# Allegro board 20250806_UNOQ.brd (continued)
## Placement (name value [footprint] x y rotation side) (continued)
NOREF#422  -  []  29.56 26.12 90 top
NOREF#423  -  []  15.97 19.8 90 top
NOREF#424  -  []  44.38 16.91 90 top
NOREF#425  -  []  30.56 15.11 90 top
NOREF#426  -  []  35.22 41.52 0 top
NOREF#427  -  []  37.81 10.46 90 top
NOREF#428  -  []  41.28 20.67 90 top
NOREF#429  -  []  43.21 22.16 90 top
NOREF#430  -  []  30.74 33.34 90 top
NOREF#431  -  []  25.85 59.93 0 top
NOREF#432  -  []  42.96 41.65 90 top
NOREF#433  -  []  42.58 43.05 0 top
NOREF#434  -  []  35.85 57.45 0 top
NOREF#435  -  []  43.94 42.96 90 top
NOREF#436  -  []  42.35 30.8 90 top
NOREF#437  -  []  44.83 47.24 90 top
NOREF#438  -  []  35.74 10.44 90 top
NOREF#439  -  []  23.52 13.83 90 top
NOREF#440  -  []  6.9 39.9 90 top
NOREF#441  -  []  29.1 20.23 0 top
NOREF#442  -  []  31.78 36.21 0 top
NOREF#443  -  []  42.95 32.67 90 top
NOREF#444  -  []  10.74 19.77 90 top
NOREF#445  -  []  11.2 13.53 0 top
NOREF#446  -  []  31.34 34.89 0 top
NOREF#447  -  []  19.52 6.27 90 top
NOREF#448  -  []  32.39 15.82 90 top
NOREF#449  -  []  50.8 22.86 90 top
NOREF#450  -  []  4.79 58.74 0 top
NOREF#451  -  []  6.37 58.11 90 top
NOREF#452  -  []  3.79 0.96 90 top
NOREF#453  -  []  36.63 30.91 90 top
NOREF#454  -  []  43.77 16.91 0 top
NOREF#455  -  []  19.33 6.3 90 top
NOREF#456  -  []  48.83 4.06 90 top
NOREF#457  -  []  22.36 5.02 90 top
NOREF#458  -  []  32.99 13.28 0 top
NOREF#459  -  []  8.07 14.25 0 top
NOREF#460  -  []  29.05 60.17 0 top
NOREF#461  -  []  24.85 57.53 90 top
NOREF#462  -  [unnamed#2]  7.62 2.54 0 top
NOREF#463  -  []  33.64 43.47 90 top
NOREF#464  -  []  7.13 25.21 90 top
NOREF#465  -  []  12.43 49.79 0 top
NOREF#466  -  []  14.43 31.45 90 top
NOREF#467  -  []  34.54 15.92 90 top
NOREF#468  -  []  26.67 39.12 90 top
NOREF#469  -  []  12.72 41.08 90 top
NOREF#470  -  []  31.13 30.25 90 top
NOREF#471  -  []  9.91 20.37 0 top
NOREF#472  -  []  43.48 62.66 0 top
NOREF#473  -  []  37.05 53.11 0 top
NOREF#474  -  []  24.49 13.62 90 top
NOREF#475  -  []  41.81 10.01 90 top
NOREF#476  -  []  43.72 4.91 0 top
NOREF#477  -  []  10.03 64.55 90 top
NOREF#478  -  []  37.77 38.26 0 top
NOREF#479  -  []  40.41 31.53 90 top
NOREF#480  -  []  45.52 29.34 0 top
NOREF#481  -  []  26.34 13.58 90 top
NOREF#482  -  []  32.63 32.16 0 top
NOREF#483  -  []  35.88 56.24 90 top
NOREF#484  -  []  30.49 4.91 90 top
NOREF#485  -  []  31.18 26.72 0 top
NOREF#486  -  []  4.23 63.64 0 top
NOREF#487  -  []  36.64 58.05 0 top
NOREF#488  -  []  17.85 31.66 0 top
NOREF#489  -  []  44.1 12.61 90 top
NOREF#490  -  []  29.47 31.59 0 top
NOREF#491  -  []  16.92 36.55 0 top
NOREF#492  -  []  41.81 20.07 0 top
NOREF#493  -  []  35.52 40.92 90 top
NOREF#494  -  []  37.33 23.09 0 top
NOREF#495  -  []  28.45 56.52 90 top
NOREF#496  -  []  28.64 34.69 0 top
NOREF#497  -  []  31.6 31.78 0 top
NOREF#498  -  []  32.39 14.81 90 top
NOREF#499  -  []  30.29 30.35 0 top
NOREF#500  -  []  35.4 11.33 90 top
NOREF#501  -  []  27.46 31.21 0 top
NOREF#502  -  []  43.3 61.16 0 top
NOREF#503  -  []  12.08 30.89 90 top
NOREF#504  -  []  41.05 40.81 90 top
NOREF#505  -  []  33.69 36.87 0 top
NOREF#506  -  []  26.23 36.61 0 top
NOREF#507  -  []  7.52 38.81 90 top
NOREF#508  -  []  34.74 55.64 0 top
NOREF#509  -  []  27.89 18.42 90 top
NOREF#510  -  []  33.16 33.88 0 top
NOREF#511  -  []  7.6 48.71 90 top
NOREF#512  -  []  44.05 4.84 90 top
NOREF#513  -  []  30.76 64.3 0 top
NOREF#514  -  []  33.32 35.82 0 top
NOREF#515  -  []  17.61 13.49 90 top
NOREF#516  -  []  6.88 27.66 0 top
NOREF#517  -  []  39.11 53.14 90 top
NOREF#518  -  []  29.76 64.3 90 top
NOREF#519  -  []  24.17 75.31 0 top
NOREF#520  -  []  43.31 43.09 0 top
NOREF#521  -  []  17.56 45.35 90 top
NOREF#522  -  []  46.36 32 0 top
NOREF#523  -  []  6.37 57.11 0 top
NOREF#524  -  []  16.72 22.08 90 top
NOREF#525  -  []  29.04 33.47 90 top
NOREF#526  -  []  9.14 28.94 90 top
NOREF#527  -  []  33.91 34.78 90 top
NOREF#528  -  []  45.39 5.84 0 top
NOREF#529  -  []  43.44 19.81 90 top
NOREF#530  -  []  9.18 33.48 90 top
NOREF#531  -  []  27.3 13.38 90 top
NOREF#532  -  []  45.12 20.64 0 top
NOREF#533  -  []  32.46 57.65 0 top
NOREF#534  -  []  28.41 33.68 90 top
NOREF#535  -  []  38.05 33.62 0 top
NOREF#536  -  []  43.21 13.46 90 top
NOREF#537  -  []  38.35 31.9 90 top
NOREF#538  -  []  17.17 13.5 90 top
NOREF#539  -  []  32.99 15.31 0 top
NOREF#540  -  []  20.08 4.76 90 top
NOREF#541  -  []  17.34 41.32 90 top
NOREF#542  -  []  13.11 6.73 90 top
NOREF#543  -  []  38.88 10.49 90 top
NOREF#544  -  []  37.06 49.13 90 top
NOREF#545  -  []  46.81 4.84 90 top
NOREF#546  -  []  27.4 36.27 0 top
NOREF#547  -  []  27.48 15.29 90 top
NOREF#548  -  []  34.16 13.43 90 top
NOREF#549  -  []  37.24 17.12 0 top
NOREF#550  -  []  33.34 44.07 0 top
NOREF#551  -  []  21.97 39.72 90 top
NOREF#552  -  []  45.62 46.92 90 top
NOREF#553  -  []  1.61 44.98 90 top
NOREF#554  -  []  29.12 30.26 90 top
NOREF#555  -  []  17.35 6.21 0 top
NOREF#556  -  []  40.47 61.23 90 top
NOREF#557  -  []  42.66 42.25 0 top
NOREF#558  -  []  21.67 39.25 0 top
NOREF#559  -  []  17.43 22.78 0 top
NOREF#560  -  []  17.59 6.09 90 top
NOREF#561  -  []  26.88 14.76 0 top
NOREF#562  -  []  7.86 63.04 0 top
NOREF#563  -  []  34.63 23.1 90 top
NOREF#564  -  []  22.61 16.36 90 top
NOREF#565  -  []  33.1 49.59 90 top
NOREF#566  -  []  43.93 45.74 0 top
NOREF#567  -  []  42.81 42.55 90 top
NOREF#568  -  []  35.22 42.03 0 top
NOREF#569  -  []  35.32 56.23 90 top
NOREF#570  -  []  33.17 37.76 90 top
NOREF#571  -  []  22.99 39.16 90 top
NOREF#572  -  []  40.64 11.38 90 top
NOREF#573  -  []  7.29 21.97 0 top
NOREF#574  -  []  32.44 43.47 90 top
NOREF#575  -  []  6.08 43.89 0 top
NOREF#576  -  []  9.19 19.77 90 top
NOREF#577  -  []  20.22 28.05 0 top
NOREF#578  -  []  10.34 35.24 0 top
NOREF#579  -  []  36.25 12.13 0 top
NOREF#580  -  []  34.92 21.9 90 top
NOREF#581  -  []  7.87 21.97 0 top
NOREF#582  -  []  7.95 19.21 90 top
NOREF#583  -  []  30.38 32 90 top
NOREF#584  -  []  14.78 13.89 90 top
NOREF#585  -  []  38.35 11.07 0 top
NOREF#586  -  []  32.19 29.83 0 top
NOREF#587  -  []  27.03 60.98 90 top
NOREF#588  -  []  46.19 16.1 90 top
NOREF#589  -  []  30.51 35.97 90 top
NOREF#590  -  []  32.47 9.99 0 top
NOREF#591  -  []  38.35 10.47 90 top
NOREF#592  -  []  25.25 59.63 0 top
NOREF#593  -  []  26.96 34.96 0 top
NOREF#594  -  []  36.8 55.69 0 top
NOREF#595  -  []  8.67 14.25 90 top
NOREF#596  -  []  33.21 30.88 0 top
NOREF#597  -  []  36.77 9.99 0 top
NOREF#598  -  []  25.47 31.36 90 top
NOREF#599  -  []  21 13.82 0 top
NOREF#600  -  []  39.14 50.07 90 top
NOREF#601  -  []  38.12 53.12 0 top
NOREF#602  -  []  10 41.54 90 top
NOREF#603  -  []  36.78 11.04 0 top
NOREF#604  -  []  9.19 20.37 0 top
NOREF#605  -  []  11.96 5.57 0 top
NOREF#606  -  []  40.25 62.67 0 top
NOREF#607  -  []  33.22 53.5 90 top
NOREF#608  -  []  8.23 13.35 90 top
NOREF#609  -  []  36.39 58.05 90 top
NOREF#610  -  []  29.35 15.6 90 top
NOREF#611  -  []  44.53 45.74 90 top
NOREF#612  -  []  29.35 16.6 0 top
NOREF#613  -  []  46.47 3.06 90 top
NOREF#614  -  []  21.67 38.14 0 top
NOREF#615  -  []  12.54 32.65 90 top
NOREF#616  -  []  26.87 33.57 0 top
NOREF#617  -  []  1.02 41.89 0 top
NOREF#618  -  []  34.54 34.83 90 top
NOREF#619  -  []  42.26 4.91 0 top
NOREF#620  -  []  7.05 35.89 90 top
NOREF#621  -  []  29.98 33.33 0 top
NOREF#622  -  []  39.45 5.2 0 top
NOREF#623  -  []  25.98 14.33 90 top
NOREF#624  -  []  29.36 30.33 0 top
NOREF#625  -  []  32.39 13.28 90 top
NOREF#626  -  []  40.75 34.5 90 top
NOREF#627  -  []  27.3 13.7 0 top
NOREF#628  -  []  7.86 57.13 0 top
NOREF#629  -  []  12.05 59.96 0 top
NOREF#630  -  []  38.88 11.09 0 top
NOREF#631  -  []  35.54 51.37 90 top
NOREF#632  -  []  10.34 35.24 0 top
NOREF#633  -  []  28.91 63.41 90 top
NOREF#634  -  []  28.01 35.75 90 top
NOREF#635  -  []  40.57 27.68 90 top
NOREF#636  -  []  22.85 28.65 0 top
NOREF#637  -  []  13.64 18.84 0 top
NOREF#638  -  []  34.18 21.03 90 top
NOREF#639  -  []  34.44 30.7 90 top
NOREF#640  -  []  46.15 45.47 0 top
NOREF#641  -  []  35 30.01 90 top
NOREF#642  -  []  20.62 13.55 0 top
NOREF#643  -  []  15.3 19.8 90 top
NOREF#644  -  []  7.05 6.52 90 top
NOREF#645  -  []  44.13 62.93 0 top
NOREF#646  -  []  34.97 61.23 0 top
NOREF#647  -  []  27.12 33.5 0 top
NOREF#648  -  []  15.32 7.12 0 top
NOREF#649  -  []  20.99 4.75 90 top
NOREF#650  -  []  13.28 53.27 0 top
NOREF#651  -  []  44.59 42.55 90 top
NOREF#652  -  []  45.02 3.61 90 top
NOREF#653  -  []  28.13 19.88 0 top
NOREF#654  -  []  37.46 27.46 0 top
NOREF#655  -  []  32.06 37.15 90 top
NOREF#656  -  []  40.55 39.2 0 top
NOREF#657  -  []  4.79 59.02 90 top
NOREF#658  -  []  36.8 56.29 90 top
NOREF#659  -  []  34.42 61.21 0 top
NOREF#660  -  []  7.1 4.77 0 top
NOREF#661  -  []  43.4 48.14 0 top
NOREF#662  -  []  41.7 5.84 0 top
NOREF#663  -  []  21.25 3.91 0 top
NOREF#664  -  []  38.81 53.74 0 top
NOREF#665  -  []  46.34 44.01 0 top
NOREF#666  -  []  33.69 37.47 90 top
NOREF#667  -  []  14.11 45.02 0 top
NOREF#668  -  []  39.75 34.98 90 top
NOREF#669  -  []  34.78 58.56 0 top
NOREF#670  -  []  27.94 32.05 0 top
NOREF#671  -  []  44.31 64.37 90 top
NOREF#672  -  []  46.36 31.4 90 top
NOREF#673  -  []  25.85 60.79 90 top
NOREF#674  -  []  6.96 38.2 0 top
NOREF#675  -  []  38.78 20.67 90 top
NOREF#676  -  []  36.4 43.64 0 top
NOREF#677  -  []  7.29 21.37 90 top
NOREF#678  -  []  44.35 43.05 0 top
NOREF#679  -  []  34.54 15.42 90 top
NOREF#680  -  []  40.62 24.12 90 top
NOREF#681  -  []  26.2 31.04 0 top
NOREF#682  -  []  14.11 16.12 0 top
NOREF#683  -  []  34.73 50.59 90 top
NOREF#684  -  []  16.17 42.24 90 top
NOREF#685  -  []  28.03 63.19 0 top
NOREF#686  -  []  19.05 34.35 90 top
NOREF#687  -  []  38.56 5.54 90 top
NOREF#688  -  []  31.59 61.55 0 top
NOREF#689  -  []  29.37 36.58 0 top
NOREF#690  -  []  22.99 39.72 90 top
NOREF#691  -  []  38.46 42.74 90 top
NOREF#692  -  []  13.51 13.89 90 top
NOREF#693  -  []  33.58 21.03 0 top
NOREF#694  -  []  29.85 17.44 0 top
NOREF#695  -  []  14.19 7.13 0 top
NOREF#696  -  []  40.04 11.38 0 top
NOREF#697  -  []  14.61 52.88 0 top
NOREF#698  -  []  28.8 52.13 90 top
NOREF#699  -  []  23.47 55.71 90 top
NOREF#700  -  []  10.62 19.31 0 top
NOREF#701  -  []  15.45 47.89 90 top
NOREF#702  -  []  31.65 19.68 90 top
NOREF#703  -  []  18.75 5.94 90 top
NOREF#704  -  []  15.55 6.28 90 top
NOREF#705  -  []  25.17 14.33 90 top
NOREF#706  -  []  34.97 61.23 0 top
NOREF#707  -  []  34.7 13.24 90 top
NOREF#708  -  []  41.81 20.67 90 top
NOREF#709  -  []  14.95 53.1 90 top
NOREF#710  -  []  44.31 23.64 90 top
NOREF#711  -  []  34.45 18.81 0 top
NOREF#712  -  []  30.56 15.71 0 top
NOREF#713  -  []  42.38 58.95 90 top
NOREF#714  -  []  14.65 53.7 0 top
NOREF#715  -  []  28.36 15.6 90 top
NOREF#716  -  []  37.07 36.55 0 top
NOREF#717  -  []  14.32 42.79 90 top
NOREF#718  -  [unnamed#2]  6.29 5.95 0 top
NOREF#719  -  []  33.69 19.45 0 top
NOREF#720  -  []  27.78 34.51 90 top
NOREF#721  -  []  37.33 24.09 90 top
NOREF#722  -  []  14.26 14.13 0 top
NOREF#723  -  []  34.42 61.21 0 top
NOREF#724  -  []  26.81 26.55 90 top
NOREF#725  -  []  43.71 18.96 0 top
NOREF#726  -  []  7.77 26.16 90 top
NOREF#727  -  []  29.64 34.16 0 top
NOREF#728  -  []  34.16 18.53 0 top
NOREF#729  -  []  44.66 57.55 90 top
NOREF#730  -  []  34.25 25.25 90 top
NOREF#731  -  []  25.47 31.96 0 top
NOREF#732  -  []  46.17 12.58 0 top
NOREF#733  -  []  34.03 23.73 0 top
NOREF#734  -  []  46.31 5.84 0 top
NOREF#735  -  []  37.07 9.39 90 top
NOREF#736  -  []  28.23 33.13 0 top
NOREF#737  -  []  13.03 14.13 0 top
NOREF#738  -  []  34.24 35.43 0 top
NOREF#739  -  []  11.56 64.08 90 top
NOREF#740  -  []  32.82 50.97 0 top
NOREF#741  -  []  28.8 53.13 90 top
NOREF#742  -  []  34.45 63.21 0 top
NOREF#743  -  []  24.51 13.9 0 top
NOREF#744  -  []  24.17 39.68 90 top
NOREF#745  -  []  43.11 3.61 90 top
NOREF#746  -  []  22.69 39.76 0 top
NOREF#747  -  []  10.95 0.32 0 top
NOREF#748  -  []  16.74 21.31 0 top
NOREF#749  -  []  33.67 9.99 90 top
NOREF#750  -  []  34.8 11.33 0 top
NOREF#751  -  []  22.4 13.52 90 top
NOREF#752  -  []  44.4 17.44 90 top
NOREF#753  -  []  31.79 14.05 90 top
NOREF#754  -  []  43.35 28.68 90 top
NOREF#755  -  []  12.97 6.31 90 top
NOREF#756  -  []  19.63 32.62 0 top
NOREF#757  -  []  8.9 21.61 90 top
NOREF#758  -  []  37.84 16.12 0 top
NOREF#759  -  []  41.02 11.02 90 top
NOREF#760  -  []  30.08 36.26 90 top
NOREF#761  -  []  7.5 27.91 90 top
NOREF#762  -  []  15.57 14.13 0 top
NOREF#763  -  []  14.49 6.53 90 top
NOREF#764  -  []  29.11 13.64 0 top
NOREF#765  -  []  4.79 44.28 90 top
NOREF#766  -  []  21.97 38.11 90 top
NOREF#767  -  []  25.91 13.55 90 top
NOREF#768  -  []  40.45 33.9 0 top
NOREF#769  -  []  7.77 26.77 0 top
NOREF#770  -  []  41.87 62.36 0 top
NOREF#771  -  []  23.47 54.71 0 top
NOREF#772  -  []  31.5 65.61 0 top
NOREF#773  -  []  51.3 58.49 90 top
NOREF#774  -  []  39.4 10.49 90 top
NOREF#775  -  []  28.5 60.17 0 top
NOREF#776  -  []  6.83 29.98 90 top
NOREF#777  -  []  29.14 37.63 0 top
NOREF#778  -  []  35.2 20.53 0 top
NOREF#779  -  []  30.46 36.59 0 top
NOREF#780  -  []  47.18 11.75 90 top
NOREF#781  -  []  44.4 62.35 90 top
NOREF#782  -  []  14.99 37.22 0 top
NOREF#783  -  []  15.55 6.31 0 top
NOREF#784  -  []  36.29 24.09 90 top
NOREF#785  -  []  18.54 31.89 90 top
NOREF#786  -  []  33.16 33.28 90 top
NOREF#787  -  [unnamed#2]  44.5 66.45 0 top
NOREF#788  -  []  38.81 54.91 0 top
NOREF#789  -  []  28.54 32.05 90 top
NOREF#790  -  []  34.65 50.16 0 top
NOREF#791  -  []  34.16 13.43 90 top
NOREF#792  -  []  40 59.64 90 top
NOREF#793  -  []  13.84 53.14 0 top
NOREF#794  -  []  32.63 36.81 0 top
NOREF#795  -  []  12.68 40.05 0 top
NOREF#796  -  []  30.75 61.3 90 top
NOREF#797  -  []  30.45 61.24 90 top
NOREF#798  -  []  8.4 28.11 0 top
NOREF#799  -  []  46.92 3.61 90 top
NOREF#800  -  []  4.8 60.35 90 top
NOREF#801  -  []  10.38 13.86 90 top
NOREF#802  -  []  32.79 30.85 90 top
NOREF#803  -  []  32.66 54.63 90 top
NOREF#804  -  []  29.29 12.65 0 top
NOREF#805  -  []  6.77 24.78 90 top
NOREF#806  -  []  12.45 0.62 90 top
NOREF#807  -  []  29.11 13.64 90 top
NOREF#808  -  []  27.46 31.75 0 top
NOREF#809  -  []  32.36 53.54 0 top
NOREF#810  -  []  33.1 31.5 0 top
NOREF#811  -  []  31.09 44.08 0 top
NOREF#812  -  []  30.64 34.38 0 top
NOREF#813  -  []  16.05 38.12 90 top
NOREF#814  -  []  22.2 13.59 90 top
NOREF#815  -  []  38.84 50.67 0 top
NOREF#816  -  []  46.07 4.91 0 top
NOREF#817  -  []  43.55 5.84 0 top
NOREF#818  -  []  46.12 20.64 90 top
NOREF#819  -  []  33.4 36.5 90 top
NOREF#820  -  []  8.5 43.1 0 top
NOREF#821  -  []  40.78 5.84 0 top
NOREF#822  -  []  14.3 6.31 0 top
NOREF#823  -  []  22.69 38.14 0 top
NOREF#824  -  []  39.45 5.8 90 top
NOREF#825  -  []  38.57 9.45 90 top
NOREF#826  -  []  25.31 36.13 90 top
NOREF#827  -  []  21.97 38.65 90 top
NOREF#828  -  []  32.67 35.37 0 top
NOREF#829  -  []  28.33 63.1 90 top
NOREF#830  -  []  31.75 49.31 90 top
NOREF#831  -  []  23.12 14.83 0 top
NOREF#832  -  []  37.59 49.13 90 top
NOREF#833  -  []  34.82 43.48 90 top
NOREF#834  -  []  36.78 11.53 90 top
NOREF#835  -  []  14.14 52.54 90 top
NOREF#836  -  []  36.82 15.58 90 top
NOREF#837  -  []  41.24 18.81 315 top
NOREF#838  -  []  22.99 37.54 90 top
NOREF#839  -  []  44.55 47.36 90 top
NOREF#840  -  []  7.6 49.73 90 top
NOREF#841  -  []  22.69 39.25 0 top
NOREF#842  -  []  13.28 53.56 0 top
NOREF#843  -  []  14.3 6.6 0 top
NOREF#844  -  []  39.59 23.12 0 top
NOREF#845  -  []  38.56 5.78 0 top
NOREF#846  -  []  32.57 50.19 0 top
NOREF#847  -  []  15.95 25.33 0 top
NOREF#848  -  []  16.46 24.05 0 top
NOREF#849  -  []  40.04 10.86 0 top
NOREF#850  -  []  33 34.44 90 top
NOREF#851  -  []  45.91 34.82 90 top
NOREF#852  -  []  9.11 18.79 0 top
NOREF#853  -  []  15.98 27.43 90 top
NOREF#854  -  []  43.21 23.17 90 top
NOREF#855  -  []  43.92 16.31 0 top
NOREF#856  -  []  47.38 4.06 0 top
NOREF#857  -  []  34.62 22.5 0 top
NOREF#858  -  []  12.17 36.63 90 top
NOREF#859  -  []  6.75 6.41 90 top
NOREF#860  -  []  6.75 7.01 0 top
NOREF#861  -  []  26.19 33.93 90 top
NOREF#862  -  []  36.25 9.39 90 top
NOREF#863  -  []  43.23 17.43 90 top
NOREF#864  -  []  17.05 23.97 90 top
NOREF#865  -  []  27.21 32.29 90 top
NOREF#866  -  []  33.98 49.31 90 top
NOREF#867  -  []  47.5 66.64 0 top
NOREF#868  -  []  20.8 13.52 90 top
NOREF#869  -  []  39.08 9.44 90 top
NOREF#870  -  []  31.83 61.28 90 top
NOREF#871  -  []  32.39 15.31 90 top
NOREF#872  -  []  37.81 11.53 90 top
NOREF#873  -  []  22.25 28.65 0 top
NOREF#874  -  []  45.62 4.91 0 top
NOREF#875  -  []  40.68 22.29 90 top
NOREF#876  -  []  7.16 19.18 90 top
NOREF#877  -  []  40.49 11.8 90 top
NOREF#878  -  []  29.26 26.72 0 top
NOREF#879  -  []  14.71 7.13 0 top
NOREF#880  -  []  43.23 16.39 90 top
NOREF#881  -  []  45.32 47.52 0 top
NOREF#882  -  []  15.54 14.13 0 top
NOREF#883  -  []  40.68 20.29 0 top
NOREF#884  -  []  12.05 58.76 90 top
NOREF#885  -  []  22.31 16.96 0 top
NOREF#886  -  []  38.27 24.83 90 top
NOREF#887  -  []  42.17 59.02 0 top
NOREF#888  -  []  23.97 39.88 0 top
NOREF#889  -  []  44.99 18.44 0 top
NOREF#890  -  []  44.47 5.84 0 top
NOREF#891  -  []  39.85 30.68 0 top
NOREF#892  -  []  27.3 13.41 0 top
NOREF#893  -  []  21.64 6.33 90 top
NOREF#894  -  []  25.74 33.17 90 top
NOREF#895  -  []  35.74 11.04 0 top
NOREF#896  -  []  25.13 34.57 90 top
NOREF#897  -  []  43.18 28.15 0 top
NOREF#898  -  []  10.56 45.83 90 top
NOREF#899  -  []  43.61 62.69 90 top
NOREF#900  -  []  43.68 47.52 90 top
NOREF#901  -  []  41.28 4.84 90 top
NOREF#902  -  []  29.05 59.57 90 top
NOREF#903  -  []  1.06 49.93 0 top
NOREF#904  -  []  35.06 50.63 90 top
NOREF#905  -  []  30.94 26.12 90 top
NOREF#906  -  []  14 19.28 0 top
NOREF#907  -  []  30.5 37.62 90 top
NOREF#908  -  []  22.69 37.57 0 top
NOREF#909  -  []  45.77 17.59 90 top
NOREF#910  -  []  36.25 11.04 0 top
NOREF#911  -  []  14.76 28.44 90 top
NOREF#912  -  []  32.99 14.81 0 top
NOREF#913  -  []  31.34 33.34 0 top
NOREF#914  -  []  36.14 51.37 0 top
NOREF#915  -  []  1.61 50.28 0 top
NOREF#916  -  []  39.95 3.93 90 top
NOREF#917  -  []  18.58 36.85 0 top
NOREF#918  -  []  36.19 53.46 0 top
NOREF#919  -  []  38.56 5.28 90 top
NOREF#920  -  []  40.31 9.38 0 top
NOREF#921  -  []  27.4 36.95 0 top
NOREF#922  -  []  44.57 3.06 90 top
NOREF#923  -  []  44.51 47.86 0 top
NOREF#924  -  []  41.28 20.07 0 top
NOREF#925  -  []  34.52 44.08 0 top
NOREF#926  -  []  30.07 31.59 90 top
NOREF#927  -  []  46.53 46.11 90 top
NOREF#928  -  []  38.22 20.23 0 top
NOREF#929  -  []  44.1 10.71 90 top
NOREF#930  -  []  12.59 53.19 90 top
NOREF#931  -  []  33.06 32.96 0 top
NOREF#932  -  []  33.92 35.31 90 top
NOREF#933  -  []  36.1 5.94 90 top
NOREF#934  -  []  8.97 23.23 0 top
NOREF#935  -  []  16.44 23.21 0 top
NOREF#936  -  []  20.41 6.27 90 top
NOREF#937  -  []  11.37 40.48 0 top
NOREF#938  -  []  35.45 26.85 0 top
NOREF#939  -  []  22.16 4.72 90 top
NOREF#940  -  []  29.05 29.62 90 top
NOREF#941  -  []  15.97 20.4 0 top
NOREF#942  -  []  31.32 14.66 90 top
NOREF#943  -  []  39.75 32.83 0 top
NOREF#944  -  []  14.64 32.39 90 top
NOREF#945  -  []  40.62 23.12 0 top
NOREF#946  -  []  46.51 34.82 0 top
NOREF#947  -  []  32.99 13.79 0 top
NOREF#948  -  []  35.37 52.86 0 top
NOREF#949  -  []  7.73 24.67 0 top
NOREF#950  -  []  40.64 10.86 90 top
NOREF#951  -  []  44.55 47.38 90 top
NOREF#952  -  []  32.04 32.67 90 top
NOREF#953  -  []  43.07 59.24 0 top
NOREF#954  -  []  43.29 23.63 90 top
NOREF#955  -  []  35.56 49.73 0 top
NOREF#956  -  []  7.6 54.01 0 top
NOREF#957  -  []  32.25 65.61 90 top
NOREF#958  -  []  32.06 38.17 90 top
NOREF#959  -  []  43.77 16.38 0 top
NOREF#960  -  []  15.85 52.5 90 top
NOREF#961  -  []  25.14 33.17 0 top
NOREF#962  -  []  36.29 23.09 0 top
NOREF#963  -  []  34.63 23.73 90 top
NOREF#964  -  []  31.32 15.17 90 top
NOREF#965  -  []  43.21 14.06 0 top
NOREF#966  -  []  8.63 20.37 0 top
NOREF#967  -  []  38.95 31.9 0 top
NOREF#968  -  []  13.03 13.63 90 top
NOREF#969  -  []  7.18 25.96 90 top
NOREF#970  -  []  42.84 57.64 90 top
NOREF#971  -  []  16.45 23.37 0 top
NOREF#972  -  []  33.39 46.89 0 top
NOREF#973  -  []  29.7 55.33 0 top
NOREF#974  -  []  13.34 20.21 0 top
NOREF#975  -  []  26.86 31.75 90 top
NOREF#976  -  []  11.2 14.13 90 top
NOREF#977  -  []  30.26 61.3 0 top
NOREF#978  -  []  8.61 28.94 90 top
NOREF#979  -  []  18.61 50.09 0 top
NOREF#980  -  []  21.17 4.72 90 top
NOREF#981  -  []  34.5 34.51 0 top
NOREF#982  -  []  16.74 22.61 90 top
NOREF#983  -  []  31.5 29.7 0 top
NOREF#984  -  []  31.47 61.95 90 top
NOREF#985  -  []  7.05 50.52 0 top
NOREF#986  -  []  8.5 32.64 0 top
NOREF#987  -  []  22.99 36.97 90 top
NOREF#988  -  []  28.91 63.42 90 top
NOREF#989  -  []  40.15 32.88 90 top
NOREF#990  -  []  10.62 14.09 0 top
NOREF#991  -  []  33.66 32.42 90 top
NOREF#992  -  []  39.59 24.12 90 top
NOREF#993  -  []  29.53 62.05 0 top
NOREF#994  -  []  13.14 34.87 90 top
NOREF#995  -  []  28.5 59.57 90 top
NOREF#996  -  []  24.51 13.62 0 top
NOREF#997  -  []  29.05 37.29 90 top
NOREF#998  -  []  29.38 33.33 90 top
NOREF#999  -  []  26.88 15.29 0 top
NOREF#1000  -  []  12.13 31.77 90 top
NOREF#1001  -  []  43.31 64.37 0 top
NOREF#1002  -  []  10.62 13.59 90 top
NOREF#1003  -  []  20.97 4.79 90 top
NOREF#1004  -  []  42.85 58.66 90 top
NOREF#1005  -  []  15.22 42.62 0 top
NOREF#1006  -  []  8.44 13.65 0 top
NOREF#1007  -  []  6.98 24 90 top
NOREF#1008  -  []  51.3 59.19 0 top
NOREF#1009  -  []  43.7 42.55 90 top
NOREF#1010  -  []  47.2 56.96 90 top
NOREF#1011  -  []  38.78 10.04 0 top
NOREF#1012  -  []  29.48 36.26 0 top
NOREF#1013  -  []  36.99 43.47 0 top
NOREF#1014  -  []  23.02 57.58 0 top
NOREF#1015  -  []  40.47 61.23 90 top
NOREF#1016  -  []  22.89 53.15 90 top
NOREF#1017  -  []  30.99 36.59 0 top
NOREF#1018  -  []  19.32 6.34 90 top
NOREF#1019  -  []  36.56 32.7 0 top
NOREF#1020  -  []  43.12 4.84 90 top
NOREF#1021  -  []  13.17 6.25 90 top
NOREF#1022  -  []  35.42 13.84 0 top
NOREF#1023  -  []  36.25 9.99 0 top
NOREF#1024  -  []  34.42 61.21 0 top
NOREF#1025  -  []  7.05 6.63 90 top
NOREF#1026  -  []  28.72 24.8 0 top
NOREF#1027  -  []  38.28 22.04 0 top
NOREF#1028  -  []  33.89 45.89 90 top
NOREF#1029  -  []  41.35 34.5 0 top
NOREF#1030  -  []  45.47 4.06 0 top
NOREF#1031  -  [unnamed#2]  35.56 2.54 0 top
NOREF#1032  -  []  43.3 62.26 0 top
NOREF#1033  -  []  36.45 13.84 0 top
NOREF#1034  -  []  25.91 36.67 0 top
NOREF#1035  -  []  43.05 42.77 90 top
NOREF#1036  -  []  14.74 50.09 90 top
NOREF#1037  -  []  38.81 54.35 0 top
NOREF#1038  -  []  30.74 34.89 90 top
NOREF#1039  -  []  15.46 46.35 0 top
NOREF#1040  -  []  38.27 10.05 0 top
NOREF#1041  -  []  46.33 33.24 0 top
NOREF#1042  -  []  35.57 28.68 90 top
NOREF#1043  -  []  32.79 9.55 90 top
NOREF#1044  -  []  8.84 29.54 0 top
NOREF#1045  -  []  16.05 13.89 90 top
NOREF#1046  -  []  34.01 9.61 90 top
NOREF#1047  -  []  30.67 62.44 90 top
NOREF#1048  -  []  22.22 13.56 90 top
NOREF#1049  -  []  29.77 40.28 0 top
NOREF#1050  -  []  24.51 13.58 90 top
NOREF#1051  -  []  43.71 43.38 90 top
NOREF#1052  -  []  15.86 7.11 0 top
NOREF#1053  -  []  18.46 5.95 90 top
NOREF#1054  -  []  15.78 49.79 0 top
NOREF#1055  -  []  28.72 13.2 90 top
NOREF#1056  -  []  29.89 12.8 0 top
NOREF#1057  -  []  9.72 49.79 90 top
NOREF#1058  -  []  33.81 30.88 90 top
NOREF#1059  -  []  28.83 33.13 90 top
NOREF#1060  -  []  35.74 11.53 90 top
NOREF#1061  -  []  32.38 34.11 90 top
NOREF#1062  -  []  35.08 57.97 90 top
NOREF#1063  -  []  36.62 51.25 0 top
NOREF#1064  -  []  26.11 13.85 90 top
NOREF#1065  -  []  30.26 61.59 0 top
NOREF#1066  -  []  38.28 23.04 90 top
NOREF#1067  -  []  18.21 13.49 0 top
NOREF#1068  -  []  39.11 52.63 90 top
NOREF#1069  -  []  45.26 18.38 90 top
NOREF#1070  -  []  27.59 19.02 0 top
NOREF#1071  -  []  35.74 12.13 0 top
NOREF#1072  -  []  36.75 13.24 90 top
NOREF#1073  -  []  28.86 62.38 0 top
NOREF#1074  -  []  2.54 17.78 90 top
NOREF#1075  -  []  8.06 50.09 90 top
NOREF#1076  -  []  30.62 22.07 90 top
NOREF#1077  -  []  28.91 13.34 90 top
NOREF#1078  -  []  39.11 53.75 90 top
NOREF#1079  -  []  15.55 53.1 0 top
NOREF#1080  -  []  11.13 64.55 0 top
NOREF#1081  -  []  20.1 4.73 90 top
NOREF#1082  -  []  42.31 57.64 90 top
NOREF#1083  -  []  22.72 24.8 0 top
NOREF#1084  -  []  35.72 13.24 90 top
NOREF#1085  -  []  43.11 4.06 90 top
NOREF#1086  -  []  39.85 30.68 90 top
NOREF#1087  -  []  42.57 19.54 90 top
NOREF#1088  -  []  31.19 16.1 0 top
NOREF#1089  -  []  26.8 32.29 0 top
NOREF#1090  -  []  16.22 36.1 90 top
NOREF#1091  -  []  45.02 4.06 90 top
NOREF#1092  -  []  45.89 4.84 90 top
NOREF#1093  -  []  26.53 36.19 0 top
NOREF#1094  -  []  17.84 5.96 90 top
NOREF#1095  -  []  21.23 3.28 0 top
NOREF#1096  -  []  44.64 58.5 90 top
NOREF#1097  -  []  28.72 13.37 0 top
NOREF#1098  -  []  31.19 15.5 90 top
NOREF#1099  -  []  15.9 37.12 90 top
NOREF#1100  -  []  42.31 58.24 0 top
NOREF#1101  -  []  20.22 6.33 0 top
NOREF#1102  -  []  35.71 8.37 90 top
NOREF#1103  -  []  42.17 59.02 0 top
NOREF#1104  -  []  6.83 30.58 0 top
NOREF#1105  -  []  37.12 50.25 90 top
NOREF#1106  -  []  43.49 42.74 90 top
NOREF#1107  -  []  28.45 37.29 0 top
NOREF#1108  -  []  28.29 38.06 90 top
NOREF#1109  -  []  38.27 23.83 0 top
NOREF#1110  -  []  32.63 37.41 90 top
NOREF#1111  -  []  32.31 34.63 90 top
NOREF#1112  -  []  34.25 24.2 90 top
NOREF#1113  -  []  45.77 18.62 0 top
NOREF#1114  -  []  16.4 38.82 90 top
NOREF#1115  -  []  44.21 21.14 0 top
NOREF#1116  -  []  31.39 61.25 90 top
NOREF#1117  -  []  26.36 32.97 90 top
NOREF#1118  -  []  30.12 19.23 90 top
NOREF#1119  -  []  8.44 61.53 90 top
NOREF#1120  -  []  32.92 10.59 0 top
NOREF#1121  -  []  30.3 62.3 0 top
NOREF#1122  -  []  30.01 30.78 90 top
NOREF#1123  -  []  33.38 21.63 0 top
NOREF#1124  -  []  13.36 16.12 0 top
NOREF#1125  -  []  31.55 37.15 90 top
NOREF#1126  -  []  35.41 8.97 0 top
NOREF#1127  -  []  32.99 14.3 0 top
NOREF#1128  -  []  7.6 52.87 90 top
NOREF#1129  -  []  28.43 19.28 90 top
NOREF#1130  -  []  40.22 9.92 0 top
NOREF#1131  -  []  3.13 62.07 0 top
NOREF#1132  -  []  31.7 58.21 90 top
NOREF#1133  -  []  17.73 22.18 90 top
NOREF#1134  -  []  43.8 23.63 90 top
NOREF#1135  -  []  34.13 11.33 90 top
NOREF#1136  -  []  23.13 13.56 0 top
NOREF#1137  -  []  40.95 61.37 0 top
NOREF#1138  -  []  38.81 52.52 0 top
NOREF#1139  -  []  42.62 42.74 90 top
NOREF#1140  -  []  24.69 13.55 90 top
NOREF#1141  -  []  37.05 17.54 0 top
NOREF#1142  -  []  44.89 57.82 90 top
NOREF#1143  -  []  8.12 38.81 0 top
NOREF#1144  -  []  7.05 6.87 0 top
NOREF#1145  -  []  27.69 38.06 0 top
NOREF#1146  -  []  25.73 34.57 0 top
NOREF#1147  -  []  36.7 43.04 90 top
NOREF#1148  -  []  28.69 12.65 90 top
NOREF#1149  -  []  25.3 35.08 90 top
NOREF#1150  -  []  32.14 44.07 0 top
NOREF#1151  -  []  29.68 37.63 0 top
NOREF#1152  -  []  45.77 18.19 0 top
NOREF#1153  -  []  31.34 33.85 0 top
NOREF#1154  -  []  51.05 66.29 90 top
NOREF#1155  -  []  31.77 50.66 90 top
NOREF#1156  -  []  33.32 35.31 0 top
NOREF#1157  -  []  45.46 27.46 0 top
NOREF#1158  -  []  12.79 53.02 90 top
NOREF#1159  -  []  1.61 49.14 90 top
NOREF#1160  -  []  31.11 35.97 0 top
NOREF#1161  -  []  16.51 25.33 0 top
NOREF#1162  -  []  15.92 36.7 0 top
NOREF#1163  -  []  12.77 36.63 0 top
NOREF#1164  -  []  14.6 19.28 90 top
NOREF#1165  -  []  9.65 60.5 90 top
NOREF#1166  -  []  10.11 19.01 0 top
NOREF#1167  -  []  38.87 11.53 90 top
NOREF#1168  -  []  8.5 38.64 0 top
NOREF#1169  -  []  36.86 27.03 0 top
NOREF#1170  -  []  39.14 50.61 90 top
NOREF#1171  -  []  32.07 35.37 90 top
NOREF#1172  -  []  23.34 59.49 90 top
NOREF#1173  -  []  24.72 38.48 90 top
NOREF#1174  -  []  31.05 30.77 90 top
NOREF#1175  -  []  12.17 36.04 90 top
NOREF#1176  -  []  4.23 62.9 0 top
NOREF#1177  -  []  26.78 34.44 0 top
NOREF#1178  -  []  17.04 41.92 0 top
NOREF#1179  -  []  28.54 31.51 90 top
NOREF#1180  -  []  21.67 37.57 0 top
NOREF#1181  -  []  46.19 16.61 90 top
NOREF#1182  -  []  35.6 6.94 0 top
NOREF#1183  -  []  27.78 35.11 0 top
NOREF#1184  -  []  46.12 22.67 90 top
NOREF#1185  -  []  32.35 35.16 90 top
NOREF#1186  -  []  35.67 52.86 90 top
NOREF#1187  -  []  11.75 30.88 90 top
NOREF#1188  -  []  26.79 30.13 90 top
NOREF#1189  -  []  44.01 24.24 0 top
NOREF#1190  -  []  38.62 59.48 0 top
NOREF#1191  -  []  13.56 18.98 0 top
NOREF#1192  -  []  9.5 38.04 90 top
NOREF#1193  -  []  42.63 15.87 0 top
NOREF#1194  -  []  31.21 61.28 0 top
NOREF#1195  -  []  14.29 6.31 90 top
NOREF#1196  -  []  33.48 34.26 0 top
NOREF#1197  -  []  27.65 12.65 90 top
NOREF#1198  -  []  27.08 35.59 90 top
NOREF#1199  -  []  39.81 31.53 0 top
NOREF#1200  -  []  22.69 38.71 0 top
NOREF#1201  -  []  5.74 49.14 90 top
NOREF#1202  -  []  30.37 63.04 0 top
NOREF#1203  -  []  22.72 24.3 90 top
NOREF#1204  -  []  23.87 75.64 0 top
NOREF#1205  -  []  28.83 32.6 90 top
NOREF#1206  -  []  22.72 18.3 90 top
NOREF#1207  -  []  31.75 35.16 0 top
NOREF#1208  -  []  12.99 14.13 0 top
NOREF#1209  -  []  3.43 61.47 90 top
NOREF#1210  -  []  17.93 24.62 90 top
NOREF#1211  -  []  29.1 19.23 90 top
NOREF#1212  -  []  34.74 56.24 90 top
NOREF#1213  -  []  22.31 16.4 0 top
NOREF#1214  -  []  44.1 61.65 90 top
NOREF#1215  -  []  33 35.04 0 top
NOREF#1216  -  []  9.11 18.79 0 top
NOREF#1217  -  []  13.03 49.79 90 top
NOREF#1218  -  []  35.14 15.92 0 top
NOREF#1219  -  []  8.44 13.65 90 top
NOREF#1220  -  []  44.97 4.84 90 top
NOREF#1221  -  []  13.6 50.29 0 top
NOREF#1222  -  []  28.66 62.62 0 top
NOREF#1223  -  []  34.57 53.94 0 top
NOREF#1224  -  []  38.31 39.22 90 top
NOREF#1225  -  []  44.21 22.16 0 top
NOREF#1226  -  []  47.01 56.99 0 top
NOREF#1227  -  []  32.77 10.29 90 top
NOREF#1228  -  []  40.85 32 90 top
NOREF#1229  -  []  38.35 11.53 90 top
NOREF#1230  -  []  28.87 63.91 0 top
NOREF#1231  -  []  21.53 14.32 0 top
NOREF#1232  -  []  37 46.32 90 top
NOREF#1233  -  []  15.11 45.02 90 top
NOREF#1234  -  []  36.22 15.58 0 top
NOREF#1235  -  []  35.57 37.88 90 top
NOREF#1236  -  []  28 36.95 90 top
NOREF#1237  -  []  32.42 33.61 90 top
NOREF#1238  -  []  33.38 13.84 0 top
NOREF#1239  -  []  11.52 43.17 0 top
NOREF#1240  -  []  32.82 51.51 0 top
NOREF#1241  -  []  18.82 32.36 0 top
NOREF#1242  -  []  28.45 35.73 0 top
NOREF#1243  -  []  30.6 61.7 90 top
NOREF#1244  -  []  17.08 46.45 0 top
NOREF#1245  -  []  33.68 49.91 0 top
NOREF#1246  -  []  31.53 38.11 0 top
NOREF#1247  -  []  21.67 39.76 0 top
NOREF#1248  -  []  16.16 6.51 90 top
NOREF#1249  -  []  10.59 14.09 0 top
NOREF#1250  -  []  32.2 67.21 90 top
NOREF#1251  -  []  17.85 33.87 0 top
NOREF#1252  -  []  27.41 35.75 0 top
NOREF#1253  -  []  37.65 52.51 90 top
NOREF#1254  -  []  27.81 32.83 0 top
NOREF#1255  -  []  29.34 13.37 90 top
NOREF#1256  -  []  49.55 3.56 0 top
NOREF#1257  -  []  31.07 33.01 0 top
NOREF#1258  -  []  42.62 5.84 0 top
NOREF#1259  -  []  12.85 5.1 0 top
NOREF#1260  -  []  30.74 33.85 90 top
NOREF#1261  -  [unnamed#2]  50.8 53.34 0 top
NOREF#1262  -  []  46.52 29.34 90 top
NOREF#1263  -  []  40 29.9 90 top
NOREF#1264  -  []  43.27 58.95 90 top
NOREF#1265  -  []  29.36 30.93 90 top
NOREF#1266  -  []  32.03 32.16 90 top
NOREF#1267  -  []  44.73 30.54 90 top
NOREF#1268  -  []  19.93 32.02 90 top
NOREF#1269  -  []  29.9 13.86 0 top
NOREF#1270  -  []  10.6 32.45 0 top
NOREF#1271  -  []  31.59 61.55 90 top
NOREF#1272  -  []  7.1 4.77 0 top
NOREF#1273  -  []  33.7 31.5 90 top
NOREF#1274  -  []  38.53 5.16 90 top
NOREF#1275  -  []  9.18 35.08 0 top
NOREF#1276  -  []  31.83 11.45 0 top
NOREF#1277  -  []  6.96 37.6 90 top
NOREF#1278  -  []  41.22 9.92 90 top
NOREF#1279  -  []  47.53 4.91 0 top
NOREF#1280  -  []  46.26 40.46 90 top
NOREF#1281  -  []  30.46 37.19 90 top
NOREF#1282  -  []  45.32 16.6 90 top
NOREF#1283  -  []  14.37 46.28 90 top
NOREF#1284  -  []  23.75 13.56 90 top
NOREF#1285  -  []  35.85 58.05 90 top
NOREF#1286  -  []  15.52 42.02 90 top
NOREF#1287  -  []  33.58 20.39 0 top
NOREF#1288  -  []  40.43 5.34 90 top
NOREF#1289  -  []  43.3 62.69 0 top
NOREF#1290  -  []  48.38 3.06 90 top
NOREF#1291  -  []  43.4 47.66 90 top
NOREF#1292  -  []  13.05 49.05 0 top
NOREF#1293  -  []  7.73 25.21 0 top
NOREF#1294  -  []  44.38 42.74 90 top
NOREF#1295  -  []  35.06 51.14 0 top
NOREF#1296  -  []  20.2 6.33 90 top
NOREF#1297  -  []  13.77 53.27 90 top
NOREF#1298  -  []  37.3 11.53 90 top
NOREF#1299  -  []  34 30.01 0 top
NOREF#1300  -  []  32.39 13.79 90 top
NOREF#1301  -  []  24.83 31.96 0 top
NOREF#1302  -  []  21 13.82 90 top
NOREF#1303  -  []  42.99 24.23 0 top
NOREF#1304  -  []  39.87 43.14 90 top
NOREF#1305  -  []  0.51 68.08 0 top
NOREF#1306  -  []  31.59 32.42 90 top
NOREF#1307  -  []  43.18 27.55 90 top
NOREF#1308  -  []  9.3 31.04 90 top
NOREF#1309  -  []  44.55 47.86 0 top
NOREF#1310  -  []  32.67 18.33 0 top
NOREF#1311  -  []  6.38 43.29 90 top
NOREF#1312  -  []  32.66 54.03 0 top
NOREF#1313  -  []  41.75 31.4 90 top
NOREF#1314  -  []  38.92 58.88 90 top
NOREF#1315  -  []  45.24 58.5 0 top
NOREF#1316  -  []  45.25 33.7 0 top
NOREF#1317  -  []  30.19 12.75 90 top
NOREF#1318  -  []  20.22 6.3 90 top
NOREF#1319  -  []  37.81 11.06 0 top
NOREF#1320  -  []  47.43 4.01 0 top
NOREF#1321  -  []  2.54 5.08 90 top
NOREF#1322  -  []  46.33 32.64 90 top
NOREF#1323  -  []  29.89 13.35 0 top
NOREF#1324  -  []  20.22 15.05 90 top
NOREF#1325  -  []  32.36 52.94 90 top
NOREF#1326  -  []  39.95 35.7 0 top
NOREF#1327  -  []  29.65 29.62 0 top
NOREF#1328  -  []  13.69 39.45 0 top
NOREF#1329  -  []  35.97 28.28 90 top
NOREF#1330  -  []  6.88 26.56 0 top
NOREF#1331  -  []  43.4 47.64 90 top
NOREF#1332  -  []  42.24 59.28 0 top
NOREF#1333  -  []  5.43 58.11 90 top
NOREF#1334  -  []  4.79 44.78 0 top
NOREF#1335  -  []  28.03 63.7 0 top
NOREF#1336  -  []  24.43 16.2 0 top
NOREF#1337  -  []  38.72 27.21 90 top
NOREF#1338  -  []  29.14 62.37 90 top
NOREF#1339  -  []  42.35 32.5 90 top
NOREF#1340  -  []  30.26 61.27 90 top
NOREF#1341  -  []  23.62 57.58 90 top
NOREF#1342  -  []  39.4 11.55 90 top
NOREF#1343  -  []  25.31 36.67 90 top
NOREF#1344  -  []  38.04 5.75 90 top
NOREF#1345  -  []  38.29 18.86 0 top
NOREF#1346  -  []  50.8 22.86 90 top
NOREF#1347  -  []  32.19 30.34 0 top
NOREF#1348  -  []  13.36 16.12 0 top
NOREF#1349  -  []  25.69 31.64 90 top
NOREF#1350  -  []  21.46 15.24 90 top
NOREF#1351  -  []  32.92 54.1 0 top
NOREF#1352  -  []  32.64 32.67 0 top
NOREF#1353  -  []  21.42 4.07 90 top
NOREF#1354  -  []  8.44 63.73 90 top
NOREF#1355  -  []  14.91 52.28 90 top
NOREF#1356  -  []  46.8 58.49 0 top
NOREF#1357  -  []  32.03 31.65 90 top
NOREF#1358  -  []  43.66 43.36 90 top
NOREF#1359  -  []  32.2 18.91 90 top
NOREF#1360  -  []  27.48 14.76 90 top
NOREF#1361  -  []  22.36 5.02 0 top
NOREF#1362  -  []  41.02 12.02 0 top
NOREF#1363  -  []  11.85 13.52 0 top
NOREF#1364  -  []  22.85 29.25 90 top
NOREF#1365  -  []  33.56 57.65 0 top
NOREF#1366  -  []  36.78 12.13 0 top
NOREF#1367  -  []  28.86 18.44 90 top
NOREF#1368  -  []  43.94 45.06 0 top
NOREF#1369  -  []  33.95 25.85 0 top
NOREF#1370  -  []  25.16 32.34 90 top
NOREF#1371  -  []  39.39 14.38 90 top
NOREF#1372  -  []  15.74 46.59 0 top
NOREF#1373  -  []  34.08 34.26 90 top
NOREF#1374  -  []  43.71 44.63 0 top
NOREF#1375  -  []  29.47 32.1 0 top
NOREF#1376  -  [unnamed#2]  2.54 54.61 0 top
NOREF#1377  -  []  29.05 36.78 90 top
NOREF#1378  -  []  26.51 27.15 0 top
NOREF#1379  -  []  40.75 41.41 0 top
NOREF#1380  -  []  11.61 16.59 90 top
NOREF#1381  -  []  45.89 16.7 0 top
NOREF#1382  -  []  21.67 38.71 0 top
NOREF#1383  -  []  43.1 31.9 90 top
NOREF#1384  -  []  35.1 34.51 90 top
NOREF#1385  -  []  31.65 30.77 0 top
NOREF#1386  -  []  22.22 13.59 0 top
NOREF#1387  -  []  36.78 10.44 90 top
NOREF#1388  -  []  15.88 47.18 0 top
NOREF#1389  -  []  30.49 3.68 90 top
NOREF#1390  -  []  28.33 62.59 90 top
NOREF#1391  -  []  29.24 34.69 90 top
NOREF#1392  -  []  21.34 6.26 90 top
NOREF#1393  -  []  33.42 29.65 90 top
NOREF#1394  -  []  28.25 12.65 0 top
NOREF#1395  -  []  47.17 12.58 90 top
NOREF#1396  -  []  44.66 57.55 0 top
NOREF#1397  -  []  43.57 4.06 0 top
NOREF#1398  -  []  38.8 51.88 0 top
NOREF#1399  -  []  20.22 6.62 0 top
NOREF#1400  -  []  13.02 53.22 90 top
NOREF#1401  -  []  37.71 39.22 0 top
NOREF#1402  -  []  30.19 12.2 90 top
NOREF#1403  -  []  31.71 34.63 0 top
NOREF#1404  -  []  29.19 63.29 90 top
NOREF#1405  -  []  27.15 38.35 0 top
NOREF#1406  -  []  26.67 37.65 90 top
NOREF#1407  -  []  29.93 36.59 0 top
NOREF#1408  -  []  17.37 13.88 90 top
NOREF#1409  -  []  14.64 33.34 90 top
NOREF#1410  -  []  33.68 13.24 90 top
NOREF#1411  -  []  36.64 51.25 0 top
NOREF#1412  -  []  31 31.78 90 top
NOREF#1413  -  []  16.26 22.23 0 top
NOREF#1414  -  []  52.6 59.64 90 top
NOREF#1415  -  []  33.92 35.82 90 top
NOREF#1416  -  []  30.5 38.22 0 top
NOREF#1417  -  []  39.87 37.51 0 top
NOREF#1418  -  []  30.11 35.75 90 top
NOREF#1419  -  []  31.82 33.61 0 top
NOREF#1420  -  []  34.13 11.93 0 top
NOREF#1421  -  []  6.96 29.05 0 top
NOREF#1422  -  []  32.79 8.95 0 top
NOREF#1423  -  []  40 33.25 90 top
NOREF#1424  -  []  38.35 12.13 0 top
NOREF#1425  -  []  31.69 37.5 0 top
NOREF#1426  -  []  15.86 13.51 90 top
NOREF#1427  -  []  36.5 47.32 0 top
NOREF#1428  -  []  43.3 61.66 90 top
NOREF#1429  -  []  11.48 31.49 0 top
NOREF#1430  -  []  32.76 57.05 90 top
NOREF#1431  -  []  45.52 4.01 0 top
NOREF#1432  -  []  32.06 37.57 0 top
NOREF#1433  -  []  45.62 45.85 90 top
NOREF#1434  -  []  22.22 13.88 0 top
NOREF#1435  -  []  28.86 17.44 0 top
NOREF#1436  -  []  21.97 37.54 90 top
NOREF#1437  -  []  14.45 43.6 90 top
NOREF#1438  -  []  42.57 20.14 0 top
NOREF#1439  -  []  8.31 29.54 0 top
NOREF#1440  -  []  38.78 20.07 0 top
NOREF#1441  -  []  13.72 40.58 90 top
NOREF#1442  -  []  13.46 39.58 90 top
NOREF#1443  -  []  31.55 36.55 0 top
NOREF#1444  -  []  25.73 13.58 0 top
NOREF#1445  -  []  14.46 29.64 0 top
NOREF#1446  -  []  33.58 19.76 0 top
NOREF#1447  -  []  19.05 34.95 0 top
NOREF#1448  -  []  47.01 57.27 0 top
NOREF#1449  -  []  40.67 18.81 0 top
NOREF#1450  -  []  38.05 31.3 0 top
NOREF#1451  -  []  13.94 18.24 90 top
NOREF#1452  -  []  11.61 15.59 90 top
NOREF#1453  -  []  41.66 4.06 0 top
NOREF#1454  -  []  26.87 32.97 90 top
NOREF#1455  -  []  43.44 18.19 0 top
NOREF#1456  -  []  30.07 32.1 90 top
NOREF#1457  -  []  6.68 24.6 0 top
NOREF#1458  -  []  37.3 12.13 0 top
NOREF#1459  -  []  9.12 49.79 0 top
NOREF#1460  -  []  3.63 61.24 0 top
NOREF#1461  -  []  33.1 50.19 0 top
NOREF#1462  -  []  8.66 50.09 0 top
NOREF#1463  -  []  9.63 28.73 90 top
NOREF#1464  -  []  27.39 30.13 0 top
NOREF#1465  -  []  14.3 6.28 90 top
NOREF#1466  -  []  32.8 36.5 0 top
NOREF#1467  -  []  29.22 24.8 0 top
NOREF#1468  -  []  39 55.87 0 top
NOREF#1469  -  []  37.97 50.54 90 top
NOREF#1470  -  []  43.8 17.44 0 top
NOREF#1471  -  []  35.2 21.48 0 top
NOREF#1472  -  []  21.98 4.75 0 top
NOREF#1473  -  []  9.56 46.43 0 top
NOREF#1474  -  []  17.3 21.31 0 top
NOREF#1475  -  []  29.51 35.75 0 top
NOREF#1476  -  []  11.79 40.34 0 top
NOREF#1477  -  []  35.06 51.14 90 top
NOREF#1478  -  []  39.4 43.42 0 top
NOREF#1479  -  []  28.31 34.52 90 top
NOREF#1480  -  []  28.86 62.38 90 top
NOREF#1481  -  []  21.83 13.72 90 top
NOREF#1482  -  []  19.23 63.73 0 top
NOREF#1483  -  []  27.12 34.1 90 top
NOREF#1484  -  []  31.2 35.75 90 top
NOREF#1485  -  []  14.9 47.39 90 top
NOREF#1486  -  []  7.32 20.61 0 top
NOREF#1487  -  []  31.17 62.55 0 top
NOREF#1488  -  []  26.79 33.93 0 top
NOREF#1489  -  []  16.38 49.79 90 top
NOREF#1490  -  []  7.65 19.81 0 top
NOREF#1491  -  []  28.86 31.36 0 top
NOREF#1492  -  []  39.11 51.92 90 top
NOREF#1493  -  []  33.5 33.7 0 top
NOREF#1494  -  []  29.22 6.18 0 top
NOREF#1495  -  []  28 36.27 90 top
NOREF#1496  -  []  39.93 6.34 0 top
NOREF#1497  -  []  44.36 62.79 90 top
NOREF#1498  -  []  43.93 42.77 90 top
NOREF#1499  -  []  37.72 57.46 90 top
NOREF#1500  -  []  34.42 61.21 90 top
NOREF#1501  -  []  10.21 19.77 90 top
NOREF#1502  -  []  13.36 16.12 0 top
NOREF#1503  -  []  8.67 13.38 90 top
NOREF#1504  -  []  13.26 39.98 0 top
NOREF#1505  -  []  48.6 57.02 90 top
NOREF#1506  -  []  24.83 31.36 90 top
NOREF#1507  -  []  11.22 19.31 90 top
NOREF#1508  -  []  43.1 13.21 0 top
NOREF#1509  -  []  39.11 51.39 90 top
NOREF#1510  -  []  34.1 33.7 90 top
NOREF#1511  -  []  8.63 19.77 90 top
NOREF#1512  -  []  33.69 19.45 0 top
NOREF#1513  -  []  29.37 37.18 90 top
NOREF#1514  -  []  41.81 4.91 0 top
NOREF#1515  -  []  37.16 32.7 90 top
NOREF#1516  -  []  45.32 46.45 0 top
NOREF#1517  -  []  29.05 36.24 90 top
NOREF#1518  -  []  29.7 33.01 90 top
NOREF#1519  -  []  8.05 13.38 0 top
NOREF#1520  -  []  34.44 31.3 0 top
NOREF#1521  -  []  15.53 6.31 90 top
NOREF#1522  -  []  22.61 15.8 90 top
NOREF#1523  -  []  19.65 49.79 90 top
NOREF#1524  -  []  31.27 51.66 0 top
NOREF#1525  -  []  13.69 40.05 90 top
NOREF#1526  -  []  39.09 14.23 90 top
NOREF#1527  -  []  43.44 18.79 90 top
NOREF#1528  -  []  39.83 38.62 90 top
NOREF#1529  -  []  21.58 3.92 90 top
NOREF#1530  -  []  25.9 35.08 0 top
NOREF#1531  -  []  29.93 37.19 90 top
NOREF#1532  -  []  31.39 43.48 90 top
NOREF#1533  -  []  29.72 35.23 0 top
NOREF#1534  -  []  39.23 38.62 0 top
NOREF#1535  -  []  26.15 38.35 90 top
NOREF#1536  -  []  44.38 16.38 90 top
NOREF#1537  -  []  13.92 20.21 0 top
NOREF#1538  -  []  22.6 4.75 90 top
NOREF#1539  -  []  31.92 14.66 0 top
NOREF#1540  -  []  11.83 32.37 0 top
NOREF#1541  -  []  37.92 55.68 0 top
NOREF#1542  -  []  7.18 27.06 90 top
NOREF#1543  -  []  31.39 21.63 90 top
NOREF#1544  -  []  24.85 58.48 90 top
NOREF#1545  -  []  10 43.14 0 top
NOREF#1546  -  []  6.21 49.48 0 top
NOREF#1547  -  []  28.89 62.5 90 top
NOREF#1548  -  []  33.53 66.41 0 top
NOREF#1549  -  []  39.01 42.75 90 top
NOREF#1550  -  []  35.43 21.9 90 top
NOREF#1551  -  []  44.1 62.25 0 top
NOREF#1552  -  []  22.18 4.67 0 top
NOREF#1553  -  []  12.09 31.7 0 top
NOREF#1554  -  []  25.91 36.13 0 top
NOREF#1555  -  []  24.72 75.11 90 top
NOREF#1556  -  []  9.51 19.01 90 top
NOREF#1557  -  []  17.3 20.71 90 top
NOREF#1558  -  []  43.44 19.21 0 top
NOREF#1559  -  []  39.3 50.88 90 top
NOREF#1560  -  []  36.25 11.53 90 top
NOREF#1561  -  []  30.99 37.19 90 top
NOREF#1562  -  []  42.05 33.1 0 top
NOREF#1563  -  []  16.92 36.25 90 top
NOREF#1564  -  []  35.32 55.63 0 top
NOREF#1565  -  []  17.08 48.05 90 top
NOREF#1566  -  []  11.38 50.09 90 top
NOREF#1567  -  []  12.12 43.48 0 top
NOREF#1568  -  []  24.87 14.93 0 top
NOREF#1569  -  []  16.89 13.62 90 top
NOREF#1570  -  []  31.5 29.1 90 top
NOREF#1571  -  []  37.67 36.55 90 top
NOREF#1572  -  []  33.53 61.86 0 top
NOREF#1573  -  []  34.57 51.14 0 top
NOREF#1574  -  []  26.01 29.28 90 top
NOREF#1575  -  []  30.61 30.78 0 top
NOREF#1576  -  []  36.94 57.45 90 top
NOREF#1577  -  []  6.86 19.78 0 top
NOREF#1578  -  []  40.19 12.4 0 top
NOREF#1579  -  []  44 32.65 90 top
NOREF#1580  -  []  15.55 6.6 0 top
NOREF#1581  -  []  24.73 15.6 90 top
NOREF#1582  -  []  33.86 57.05 90 top
NOREF#1583  -  []  17.35 4.77 90 top
NOREF#1584  -  []  29.12 30.86 0 top
NOREF#1585  -  []  41.81 10.61 0 top
NOREF#1586  -  []  39.44 43.11 90 top
NOREF#1587  -  []  15.98 26.83 0 top
NOREF#1588  -  []  20.99 5.07 0 top
NOREF#1589  -  []  43.16 62.9 0 top
NOREF#1590  -  []  21.16 6.33 0 top
NOREF#1591  -  []  30.12 20.23 0 top
NOREF#1592  -  []  30.04 34.38 90 top
NOREF#1593  -  []  16.17 41.24 0 top
NOREF#1594  -  []  25.25 59.23 90 top
NOREF#1595  -  []  34.13 49.99 0 top
NOREF#1596  -  []  34.2 20.53 90 top
NOREF#1597  -  []  35.78 9.66 90 top
NOREF#1598  -  []  28.86 31.96 90 top
NOREF#1599  -  []  37.9 35.25 0 top
NOREF#1600  -  []  15.62 6.52 90 top
NOREF#1601  -  []  28.45 36.78 0 top
NOREF#1602  -  []  39.97 27.68 0 top
NOREF#1603  -  []  25.14 33.68 0 top
NOREF#1604  -  []  7.13 24.67 90 top
NOREF#1605  -  []  20.04 4.61 0 top
NOREF#1606  -  []  43.16 62.9 0 top
NOREF#1607  -  []  29.7 32.41 0 top
NOREF#1608  -  []  46.53 46.66 90 top
NOREF#1609  -  []  21.16 6.61 0 top
NOREF#1610  -  []  7.05 53.66 0 top
NOREF#1611  -  []  28.36 33.89 0 top
NOREF#1612  -  []  16.51 25.93 90 top
NOREF#1613  -  []  23.52 13.83 0 top
NOREF#1614  -  []  27.81 32.29 0 top
NOREF#1615  -  []  24.72 74.04 90 top
NOREF#1616  -  []  45.01 38.4 180 bottom
NOREF#1617  -  [unnamed#2]  45.34 65.79 180 bottom
NOREF#1618  -  [unnamed#2]  36.52 21.84 180 bottom
NOREF#1619  -  [unnamed#2]  3.15 60.94 180 bottom
PMIC1  PM-4125-3-NSP194-TR-01-0  [BGA194_67X83_0D566_H10_QUALCOMM]  37.84 16.12 180 top
Q2707  MMDT3904-7-F_SOT363_6P  [SOT363_6P_22X21_H110]  44 31.9 180 bottom
Q2708  MMDT3904-7-F_SOT363_6P  [SOT363_6P_22X21_H110]  39.1 33.9 0 bottom
Q2709  MMDT3904-7-F_SOT363_6P  [SOT363_6P_22X21_H110]  40.9 29.9 180 bottom
Q2801  PJA3413_SOT23_3P  [SOT23_29X24_H110]  14.25 48.84 270 bottom
Q2802  MMBT3904W_SOT323_3P  [SOT323_21X20_H110]  16.51 46.18 270 bottom
QWIIC1  CI1104M1HR0-NH  [WTB4_60X51_1_H32_D90]  14.35 3.05 90 top
R501  0  [R0201_H030]  43.65 23.93 180 top
R502  0  [R0201_H030]  43.14 23.93 180 top
R503  0  [R0201_H030]  44.16 23.94 180 top
R601  47K  [R0201_H030]  40.34 12.1 90 top
R603  0  [R0201_H030]  46.04 16.4 270 top
R604  0  [R0201_H030]  46.04 16.91 270 top
R605  7.5K_1%  [R0201_H030]  38.93 9.74 0 top
R606  100K  [R0201_H030]  38.42 9.75 0 top
R607  56K  [R0201_H030]  44.07 16.01 270 top
R701  22  [R0201_H030]  30.04 13.05 90 top
R702  0  [R0201_H030]  30.05 13.56 90 top
R703  0  [R0201_H030]  30.04 12.5 90 top
R705  0  [R0201_H030]  36.92 9.7 0 top
R706  0  [R0201_H030]  35.63 9.96 270 top
R707  5.1K  [R0201_H030]  36.4 10.74 0 top
R708  0  [R0201_H030]  38.86 43.05 180 top
R709  0  [R0201_H030]  35.56 8.67 270 top
R901  0  [R0201_H030]  34.77 22.2 180 top
R902  0  [R0201_H030]  35.28 22.2 180 top
R1101  10K_1%  [R0201_H030]  16.07 36.4 270 bottom
R1102  10K_1%  [R0201_H030]  19.78 32.32 90 bottom
R1201  0  [R0201_H030]  23 25.16 180 top
R1202  100_1%  [R0201_H030]  31.84 26.42 0 top
R1203  4.02K_1%  [R0201_H030]  31.33 26.42 0 top
R1204  0  [R0201_H030]  6.36 49.18 90 top
R1205  0  [R0201_H030]  21.99 23.52 180 top
R1206  0  [R0201_H030]  22.47 21.09 180 top
R1207  22  [R0201_H030]  35.6 26.55 90 top
R1208  1K  [R0201_H030]  26.66 26.85 90 top
R1301  0  [R0201_H030]  23.51 25.16 0 top
R1302  0  [R0201_H030]  23.85 26.31 0 top
R1303  2.2K  [R0201_H030]  21.82 37.27 90 top
R1304  0  [R0201_H030]  22.84 37.27 90 top
R1305  2.2K  [R0201_H030]  21.82 38.41 90 top
R1306  0  [R0201_H030]  22.84 38.41 90 top
R1307  2.2K  [R0201_H030]  21.82 37.84 90 top
R1308  0  [R0201_H030]  22.84 37.84 90 top
R1309  2.2K  [R0201_H030]  21.82 38.95 90 top
R1310  0  [R0201_H030]  22.84 38.95 90 top
R1311  2.2K  [R0201_H030]  27.74 18.72 180 top
R1312  0  [R0201_H030]  28.28 19.58 90 top
R1313  2.2K  [R0201_H030]  22.46 16.1 270 top
R1314  0  [R0201_H030]  22.46 16.66 90 top
R1315  10K_1%  [R0201_H030]  21.82 39.46 90 top
R1316  10K_1%  [R0201_H030]  22.84 39.46 90 top
R1317  10K_1%  [R0201_H030]  21.82 40.02 90 top
R1318  10K_1%  [R0201_H030]  22.84 40.02 90 top
R1319  10K_1%  [R0201_H030]  25.15 15.9 180 top
R1320  10K_1%  [R0201_H030]  24.58 15.9 0 top
R1321  0  [R0201_H030]  38.31 43.04 0 top
R1401  240_1%  [R0201_H030]  34.39 35.13 180 bottom
R1501  0  [R0201_H030]  38.99 50.37 90 top
R1502  0  [R0201_H030]  38.99 50.91 90 top
R1503  0  [R0201_H030]  38.96 51.69 90 top
R1504  0  [R0201_H030]  38.96 52.22 90 top
R1505  0  [R0201_H030]  36.91 49.43 0 top
R1506  0  [R0201_H030]  37.44 49.43 0 top
R1507  0  [R0201_H030]  38.96 52.93 90 top
R1508  0  [R0201_H030]  38.96 53.44 90 top
R1509  0  [R0201_H030]  35.71 49.43 0 top
R1510  0  [R0201_H030]  36.22 49.43 0 top
R1522  1.4K_1%  [R0201_H030]  30.79 26.42 0 top
R1601  3.01K_1%  [R0201_H030]  29.41 26.42 0 top
R1602  6.04K_1%  [R0201_H030]  35.37 41.22 270 top
R2113  10K_1%  [R0201_H030]  34.1 24.5 180 bottom
R2114  10K_1%  [R0201_H030]  34.1 25.55 180 bottom
R2201  240_1%  [R0201_H030]  40.9 41.11 90 bottom
R2202  240_1%  [R0201_H030]  42.81 41.95 270 bottom
R2501  0  [R0201_H030]  6.62 25.08 0 bottom
R2502  0  [R0201_H030]  7.03 27.36 0 bottom
R2503  0  [R0201_H030]  6.83 24.3 90 bottom
R2504  0  [R0201_H030]  7.03 26.26 0 bottom
R2505  0  [R0201_H030]  16.38 24.66 270 bottom
R2506  0  [R0201_H030]  17.78 24.92 270 bottom
R2507  0  [R0201_H030]  16.59 22.91 90 bottom
R2508  0  [R0201_H030]  7.47 20.31 90 bottom
R2509  0  [R0201_H030]  10.59 20.07 180 bottom
R2511  0  [R0201_H030]  10.06 20.07 180 bottom
R2512  1M  [R0201_H030]  13.79 18.54 270 bottom
R2513  0  [R0201_H030]  13.49 19.91 180 bottom
R2514  0  [R0201_H030]  14.07 19.91 0 bottom
R2515  100K  [R0201_H030]  46.3 45.17 0 bottom
R2516  0  [R0201_H030]  6.52 26.58 0 bottom
R2605  1K  [R0201_H030]  14.76 52.58 180 bottom
R2606  1K  [R0201_H030]  15.7 52.8 180 bottom
R2607  0  [R0201_H030]  14.8 53.4 90 bottom
R2608  0  [R0201_H030]  13.99 52.84 90 bottom
R2609  1K  [R0201_H030]  30.52 62.74 90 bottom
R2610  1K  [R0201_H030]  29.68 61.75 180 bottom
R2611  0  [R0201_H030]  30.45 62 270 bottom
R2612  0  [R0201_H030]  31.32 62.25 180 bottom
R2613  2.2K  [R0201_H030]  14.34 6.83 180 top
R2614  2.2K  [R0201_H030]  16.01 6.81 180 top
R2615  0  [R0201_H030]  15.47 6.82 0 top
R2616  0  [R0201_H030]  14.86 6.83 0 top
R2617  0  [R0201_H030]  21.43 4.22 90 top
R2618  0  [R0201_H030]  21.4 3.61 90 top
R2619  0  [R0201_H030]  21.38 2.98 90 top
R2621  100K  [R0201_H030]  6.23 43.59 0 bottom
R2622  2.2K  [R0201_H030]  6.9 36.19 90 bottom
R2623  0  [R0201_H030]  17.58 22.48 270 bottom
R2624  0  [R0201_H030]  7.01 19.48 180 bottom
R2625  0  [R0201_H030]  7.8 19.51 180 bottom
R2626  0  [R0201_H030]  7.11 28.75 90 bottom
R2631  0  [R0201_H030]  25.83 14.63 0 bottom
R2632  0  [R0201_H030]  25.02 14.63 0 bottom
R2633  0  [R0201_H030]  21.68 14.02 0 bottom
R2634  0  [R0201_H030]  23.27 14.53 0 bottom
R2635  0  [R0201_H030]  22.73 14.53 0 bottom
R2636  0  [R0201_H030]  22.33 4.37 270 bottom
R2637  0  [R0201_H030]  21.27 4.37 90 bottom
R2638  0  [R0201_H030]  28.18 63.4 270 bottom
R2639  0  [R0201_H030]  28.18 62.89 270 bottom
R2640  0  [R0201_H030]  8.99 29.24 0 bottom
R2641  0  [R0201_H030]  8.46 29.24 0 bottom
R2642  2.2K  [R0201_H030]  45.47 47.22 180 bottom
R2643  2.2K  [R0201_H030]  45.47 46.15 0 bottom
R2644  0  [R0201_H030]  46.38 46.41 270 bottom
R2645  0  [R0201_H030]  46.38 46.96 270 bottom
R2646  0  [R0201_H030]  20.19 4.31 90 bottom
R2660  220K  [R0201_H030]  33.71 57.35 90 top
